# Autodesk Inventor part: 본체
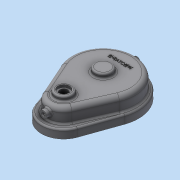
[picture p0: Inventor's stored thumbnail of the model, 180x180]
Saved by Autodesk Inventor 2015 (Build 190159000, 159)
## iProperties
Created: 2024-05
Part Number: 본체
Material: 알루미늄 6061
Document SubType Name: Modeling
Designer: Administrator
Density: 2.7 g/cm^3
Appearance: 기본값
Mass: 654.577 g
Surface Area: 714.142 cm^2
Volume: 242.436 cm^3
Author: Administrator
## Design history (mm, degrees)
sketch "스케치16"
  geometry: L1 (-51.182, 46.275)-(-25.591, -11.362); L2 (25.591, -11.362)-(51.182, 46.275); A1 r 28 centre (0, 0) between (-25.591, -11.362) and (25.591, -11.362); A2 r 56 centre (0, 69) between (-51.182, 46.275) and (51.182, 46.275); 1 further point
  constraints: 4 end point, 4 point on circle, 4 tangent, 2 centre point, 1 coincident, 1 vertical alignment
  dimensions: "d52" = 56 diameter of A1; "d53" = 112 diameter of A2; "d54" = 69 distance of point (0, 0) A2.centre
extrude "돌출10" new body sketch "스케치16" distance "d55" = 25; taper "d56" = 0 deg
feature "쉘3" dims "d57" = 5
sketch "스케치17"
  geometry: L1 (46.612, 48.304)-(21.021, -9.333) reference; L2 (-21.021, -9.333)-(-46.612, 48.304) reference; L3 (-25.591, -11.362)-(-51.182, 46.275) reference; L4 (51.182, 46.275)-(25.591, -11.362) reference; L5 (-36.77, -13)-(-58.454, 48.333); L6 (36.77, -13)-(58.454, 48.333); L7 (-51.182, 46.275)-(-25.591, -11.362); L8 (25.591, -11.362)-(51.182, 46.275); L9 (-46.612, 48.304)-(-21.021, -9.333); L10 (21.021, -9.333)-(46.612, 48.304); A1 r 51 centre (0, 69) between (46.612, 48.304) and (-46.612, 48.304) reference; A2 r 23 centre (0, 0) between (-21.021, -9.333) and (21.021, -9.333) reference; A3 r 28 centre (0, 0) between (-25.591, -11.362) and (25.591, -11.362) reference; A4 r 56 centre (0, 69) between (51.182, 46.275) and (-51.182, 46.275) reference; A5 r 39 centre (0, 0) between (-33.802, 19.453) and (33.802, 19.453); A6 r 62 centre (0, 69) between (32.305, 16.081) and (-32.305, 16.081); A7 r 28 centre (0, 0) between (-27.501, 5.261) and (27.501, 5.261); A8 r 56 centre (0, 69) between (37.226, 27.164) and (-37.226, 27.164); A9 r 51 centre (0, 69) between (46.612, 48.304) and (-46.612, 48.304); A10 r 23 centre (0, 0) between (-21.021, -9.333) and (21.021, -9.333)
  constraints: 17 point on circle, 15 tangent, 12 end point, 12 point on line, 6 centre point, 6 coincident, 4 collinear, 1 concentric
  dimensions: "d58" = 124 diameter of A6; "d59" = 78 diameter of A5
extrude "돌출11" join sketch "스케치17" distance "d60" = 15; taper "d61" = 0 deg
sketch "스케치18"
  geometry: C1 r 15 at (0, 69); C2 r 15 at (0, 0); A1 r 56 centre (0, 69) between (51.182, 46.275) and (-51.182, 46.275) reference; A2 r 28 centre (0, 0) between (-25.591, -11.362) and (25.591, -11.362) reference
  constraints: 2 centre point, 2 coincident, 1 equal radius
  dimensions: "d62" = 30 diameter of C1
extrude "돌출12" join sketch "스케치18" distance "d63" = 8; taper "d64" = 0 deg
node "작업 평면3"
sketch "스케치19"
  geometry: L1 (-36.77, -15)-(36.77, -15) reference; C1 r 6 at (0, 13); 1 further point
  constraints: 1 centre point, 1 vertical alignment
  dimensions: "d66" = 28 distance from line of L1 C1.centre; "d67" = 12 diameter of C1
extrude "돌출13" join sketch "스케치19" stored distance "d68" = 8; taper "d69" = 0 deg
node "작업 평면4"
sketch "스케치20"
  geometry: L1 (51, -15)-(-51, -15) reference; C1 r 6 at (0, 13); 3 further points
  constraints: 1 centre point, 1 vertical alignment
  dimensions: "d71" = 12 diameter of C1; "d72" = 28 distance from line of L1 C1.centre
extrude "돌출14" join sketch "스케치20" stored distance "d73" = 8; taper "d74" = 0 deg
sketch "스케치21"
  geometry: C1 r 14 at (0, -69); C2 r 14 at (0, 0); A1 r 51 centre (0, 0) between (46.612, -20.696) and (-46.612, -20.696) reference; A2 r 23 centre (0, -69) between (-21.021, -78.333) and (21.021, -78.333) reference
  constraints: 2 centre point, 2 coincident, 1 equal radius
  dimensions: "d75" = 28 diameter of C1
extrude "돌출15" join sketch "스케치21" distance "d76" = 8; taper "d77" = 0 deg
sketch "스케치22"
  geometry: C1 r 15 at (0, 69) reference; 1 further point
  constraints: 1 vertical alignment, 1 other
  dimensions: "d78" = 30 distance of C1.centre point (0, 99)
feature "엠보싱2" sketch "스케치22" dims "d52" = 56, "d53" = 112, "d54" = 69, "d58" = 124, "d59" = 78, "d79" = 0.5, "d80" = 0
hole "구멍2" diameter "d83" = 14; stored, may be unused: countersink angle "d87" = 90 deg, drill point angle "d89" = 118 deg; dims "d81" = 10, "d82" = 10, "d84" = 8, "d85" = 20, "d86" = 4.2, "d88" = 10
hole "구멍3" diameter "d92" = 5.188; stored, may be unused: countersink angle "d96" = 90 deg, drill point angle "d98" = 118 deg; dims "d90" = 10, "d91" = 10, "d93" = 12, "d94" = 7, "d95" = 2, "d97" = 16
hole "구멍4" diameter "d101" = 5.188; stored, may be unused: countersink angle "d105" = 90 deg, drill point angle "d107" = 118 deg; dims "d99" = 10, "d100" = 10, "d102" = 12, "d103" = 7, "d104" = 2, "d106" = 16
hole "구멍5" diameter "d110" = 14; stored, may be unused: countersink angle "d114" = 90 deg, drill point angle "d116" = 120 deg; dims "d108" = 10, "d109" = 10, "d111" = 12, "d112" = 5, "d113" = 4.2, "d115" = 10
sketch "스케치23"
  geometry: L1 (0, 69)-(0, 22.075); A1 r 51 centre (0, 69) between (46.612, 48.304) and (-46.612, 48.304) reference; A2 r 23 centre (0, 0) between (-21.021, -9.333) and (21.021, -9.333) reference; A3 r 62 centre (0, 69) between (58.454, 48.333) and (-58.454, 48.333) reference; 10 further points
  constraints: 3 horizontal alignment, 2 end point, 1 symmetric about line, 1 vertical, 8 other
  dimensions: "d118" = 56 distance of point (56, 69) A1.centre; "d121" = 180 deg dimension on A1.centre point (56, 69) point (-56, 69); "d123" = 34 vertical distance of point (-48.741, 35) point (-56, 69); "d124" = 33 distance of A2.centre point (-33, 0); "d127" = 180 deg dimension on A2.centre point (-33, 0) point (33, 0)
hole "구멍6" sketch "스케치23" at (56, 69), (39.598, 108.598), (0, 125), (-39.598, 108.598), (-56, 69), (-48.741, 35), (48.741, 35), (-33, 0), (0, -33), (33, 0) diameter "d129" = 3.242; stored, may be unused: countersink angle "d133" = 90 deg, drill point angle "d135" = 120 deg; dims "d130" = 8, "d131" = 5, "d132" = 4.2, "d134" = 10
fillet "모깎기1" dims "d136" = 8
fillet "모깎기2" dims "d137" = 3
chamfer "모따기1" distance "d138" = 1; stored, may be unused: second distance "d139" = 2, angle "d140" = 45 deg
chamfer "모따기2" distance "d141" = 0.4; stored, may be unused: second distance "d142" = 2, angle "d143" = 30 deg
node "솔리드3"
other parameters: "d65" = -36, "d70" = 128
